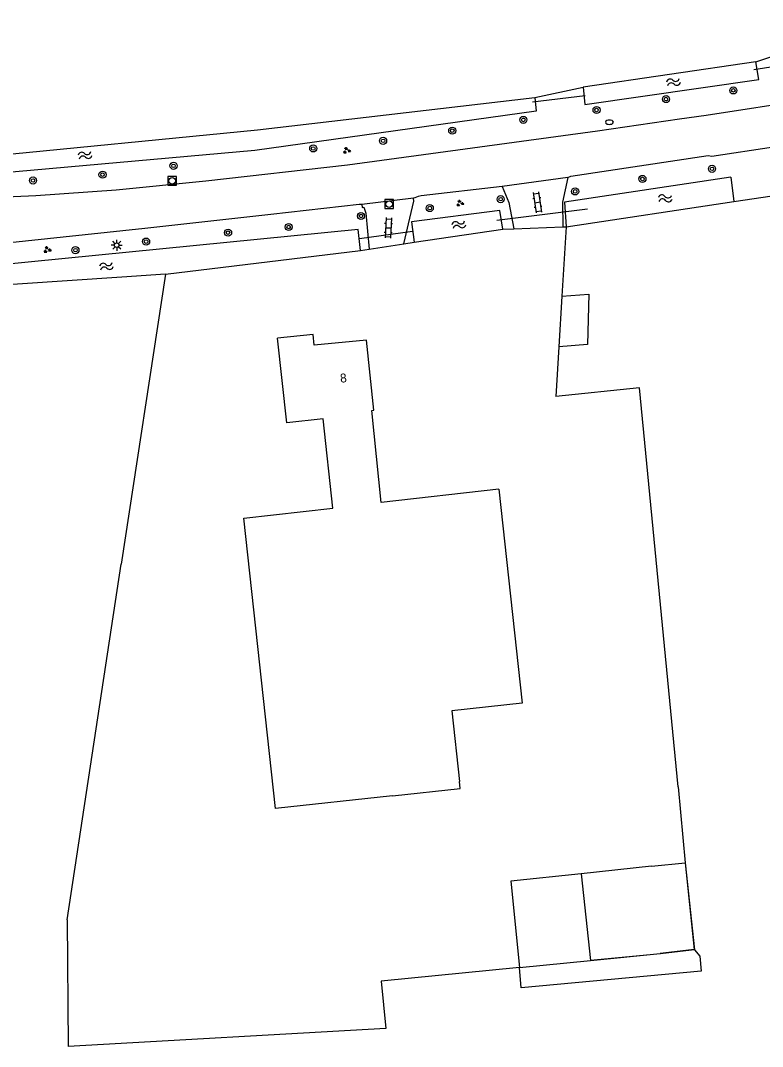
# Model space of a CAD drawing. Extents: x 124000 to 129000, y 395500 to 397503.
# Drawn here: x 125043 to 125126.8, y 396182.9 to 396298.7 of the extents above; entities that cross this region are included whole.
import ezdxf

# ---------------------------------------------------------------- set-up
doc = ezdxf.new("R2010")
doc.units = 0
for name, color, linetype in [('gg-afsc-hekwerk', 7, 'Continuous'), ('gg-anno-huisnummerreeks BGT', 7, 'Continuous'), ('gg-bbg-bijgebouw', 7, 'Continuous'), ('gg-bbg-gedigitaliseerde bebouwing', 7, 'Continuous'), ('gg-bbg-gedigitaliseerde bijgebouw', 7, 'Continuous'), ('gg-bbg-hoofdgebouw', 7, 'Continuous'), ('gg-bbg-luifel en loopbrug', 7, 'Continuous'), ('gg-knt-bronhoudergrens', 7, 'Continuous'), ('gg-knt-verharding', 7, 'Continuous'), ('gg-kntw-bovenkant insteek waterloop', 7, 'Continuous'), ('gg-kwrk-duiker nz buis', 7, 'Continuous'), ('gt-grn-groengrens', 7, 'Continuous'), ('gt-grn-weggrens', 7, 'Continuous'), ('gt-symb-boom', 7, 'Continuous'), ('gt-symb-brandkraan', 7, 'Continuous'), ('gt-symb-groenvak', 7, 'Continuous'), ('gt-symb-klinker verharding', 7, 'Continuous'), ('gt-symb-lichtmast', 7, 'Continuous'), ('gt-symb-rioolschacht', 7, 'Continuous'), ('gt-symb-watersymbool', 7, 'Continuous'), ('gx-grn-maaiveld', 7, 'Continuous')]:
    doc.layers.add(name, color=color, linetype=linetype)

# ---------------------------------------------------------------- blocks, each defined once
blk = doc.blocks.new('gt0-BOOM')
at = {"layer": 'gt-symb-boom'}
for radius in [0.4, 0.2]:
    blk.add_circle((0, 0), radius, dxfattribs=at)
blk = doc.blocks.new('gt0-WA')
at = {"layer": 'gt-symb-watersymbool'}
for centre, start, end in [((-0.32, 0.02), 28.0725, 151.9275), ((0.43, 0.42), 208.0725, 331.9275), ((-0.32, -0.43), 28.0725, 151.9275), ((0.43, -0.03), 208.0725, 331.9275)]:
    blk.add_arc(centre, 0.425, start, end, dxfattribs=at)
blk = doc.blocks.new('gt0-BR')
at = {"layer": 'gt-symb-brandkraan'}
for centre, radius, start, end in [((-0.24, 0), 0.206, 107.5669, 252.4331), ((0.6, -2.66), 3, 106.892, 107.5669), ((0, -0.69), 0.938, 73.108, 106.892), ((-0.6, -2.66), 3, 72.4331, 73.108), ((0.24, 0), 0.206, 287.567, 72.4331), ((0.6, 2.66), 3, 252.4331, 253.108), ((0, 0.69), 0.938, 253.108, 286.8921), ((-0.6, 2.66), 3, 286.8921, 287.567)]:
    blk.add_arc(centre, radius, start, end, dxfattribs=at)
blk = doc.blocks.new('gt0-GRVAK')
at = {"layer": 'gt-symb-groenvak'}
for p, q in [((-0.11, 0.19), (-0.23, 0.24)), ((-0.18, 0.15), (0.09, 0.15)), ((-0.09, 0.21), (-0.16, 0.32)), ((-0.05, 0.21), (-0.05, 0.39)), ((0, 0.21), (0.06, 0.32)), ((0.01, 0.19), (0.13, 0.24)), ((0.26, -0.05), (0.2, 0.06)), ((0.3, -0.05), (0.3, 0.13)), ((0.35, -0.05), (0.41, 0.06)), ((-0.25, -0.23), (-0.36, -0.18)), ((-0.32, -0.26), (-0.05, -0.26)), ((-0.23, -0.21), (-0.29, -0.09)), ((-0.18, -0.2), (-0.18, -0.02)), ((-0.14, -0.21), (-0.07, -0.09)), ((-0.12, -0.23), (0, -0.18)), ((0.24, -0.07), (0.12, -0.02)), ((0.17, -0.11), (0.44, -0.11)), ((0.37, -0.07), (0.49, -0.02))]:
    blk.add_line(p, q, dxfattribs=at)
blk = doc.blocks.new('gt0-KL1')
at = {"layer": 'gt-symb-klinker verharding'}
for p, q in [((-1.15, 0.3), (1.15, 0.3)), ((-1, -0.3), (-1, 0.3)), ((-0.5, 0.3), (-0.5, 0.45)), ((0, -0.3), (0, 0.3)), ((0.5, 0.3), (0.5, 0.45)), ((1, -0.3), (1, 0.3)), ((-1.15, -0.3), (1.15, -0.3)), ((-0.5, -0.45), (-0.5, -0.3)), ((0.5, -0.45), (0.5, -0.3))]:
    blk.add_line(p, q, dxfattribs=at)
blk = doc.blocks.new('gt0-RS')
at = {"layer": 'gt-symb-rioolschacht'}
blk.add_lwpolyline([(-0.5, -0.5), (0.5, -0.5), (0.5, 0.5), (-0.5, 0.5)], close=True, dxfattribs=at)
blk.add_circle((0, 0), 0.375, dxfattribs=at)
blk = doc.blocks.new('gt0-LMAST')
at = {"layer": 'gt-symb-lichtmast'}
for p, q in [((-0.18, 0.17), (-0.45, 0.44)), ((-0.01, 0.25), (-0.01, 0.62)), ((0.17, 0.17), (0.44, 0.44)), ((-0.26, 0), (-0.63, 0)), ((-0.18, -0.18), (-0.45, -0.45)), ((-0.01, -0.25), (-0.01, -0.63)), ((0.44, -0.45), (0.17, -0.18)), ((0.24, 0), (0.62, 0))]:
    blk.add_line(p, q, dxfattribs=at)
blk.add_circle((-0.01, 0), 0.25, dxfattribs=at)

msp = doc.modelspace()

# ---------------------------------------------------------------- linework, layer by layer
at = {"layer": 'gg-afsc-hekwerk'}
for p, q in [((125123.53, 396278.23), (125128.9, 396279.04)), ((125123.53, 396278.23), (125128.9, 396279.04)), ((125104.6, 396275.38), (125123.53, 396278.23)), ((125104.6, 396275.38), (125123.53, 396278.23)), ((125104.6, 396275.38), (125104.12, 396267.53)), ((125104.6, 396275.38), (125104.12, 396267.53)), ((125059.35, 396270.03), (125054.36, 396237.31)), ((125059.35, 396270.03), (125054.36, 396237.31)), ((125059.35, 396270.03), (125054.41, 396269.7)), ((125059.35, 396270.03), (125054.41, 396269.7)), ((125104.12, 396267.53), (125103.77, 396261.82)), ((125103.77, 396261.82), (125103.43, 396256.23)), ((125103.77, 396261.82), (125103.43, 396256.23)), ((125048.24, 396197.18), (125054.36, 396237.31)), ((125048.24, 396197.18), (125054.36, 396237.31)), ((125084.22, 396184.9), (125048.34, 396182.87)), ((125084.22, 396184.9), (125048.34, 396182.87))]:
    msp.add_line(p, q, dxfattribs=at)
for points in [[(125054.41, 396269.7), (125025.77, 396267.78), (125023.5, 396267.74)], [(125054.41, 396269.7), (125025.77, 396267.78), (125023.5, 396267.74)], [(125099.32, 396191.79), (125083.7, 396190.24), (125084.22, 396184.9)], [(125099.32, 396191.79), (125083.7, 396190.24), (125084.22, 396184.9)]]:
    msp.add_lwpolyline(points, dxfattribs=at)
at = {"layer": 'gg-bbg-bijgebouw'}
msp.add_line((125099.32, 396191.79), (125107.37, 396192.58), dxfattribs=at)
msp.add_lwpolyline([(125106.31, 396202.37), (125098.35, 396201.53), (125099.32, 396191.79)], dxfattribs=at)
at = {"layer": 'gg-bbg-gedigitaliseerde bebouwing'}
for points in [[(125084.98, 396211.15), (125071.79, 396209.71), (125068.2, 396242.51), (125078.25, 396243.61), (125077.15, 396253.69), (125073.04, 396253.24), (125072, 396262.79)], [(125097.01, 396245.75), (125099.65, 396221.63), (125091.68, 396220.76), (125092.56, 396212.77)], [(125084.98, 396211.15), (125092.64, 396211.99), (125092.56, 396212.77)]]:
    msp.add_lwpolyline(points, dxfattribs=at)
at = {"layer": 'gg-bbg-gedigitaliseerde bijgebouw'}
msp.add_line((125106.31, 396202.37), (125107.37, 396192.58), dxfattribs=at)
at = {"layer": 'gg-bbg-hoofdgebouw'}
msp.add_lwpolyline([(125097.01, 396245.75), (125083.7, 396244.26), (125082.64, 396254.66), (125082.87, 396254.68), (125082.06, 396262.58), (125076.15, 396262.02), (125076.02, 396263.22), (125072, 396262.79)], dxfattribs=at)
at = {"layer": 'gg-bbg-luifel en loopbrug'}
for p, q in [((125114.26, 396203.21), (125106.31, 396202.37)), ((125107.37, 396192.58), (125115.24, 396193.36))]:
    msp.add_line(p, q, dxfattribs=at)
msp.add_lwpolyline([(125114.26, 396203.21), (125118.03, 396203.58), (125119.06, 396193.8), (125115.24, 396193.36)], dxfattribs=at)
at = {"layer": 'gg-knt-bronhoudergrens'}
for p, q in [((125112.89, 396257.22), (125103.43, 396256.23)), ((125117.27, 396212.16), (125112.89, 396257.22)), ((125117.27, 396212.16), (125118.03, 396203.58)), ((125118.03, 396203.58), (125119.09, 396193.78)), ((125048.24, 396197.18), (125048.34, 396182.87))]:
    msp.add_line(p, q, dxfattribs=at)
for points in [[(125104.12, 396267.53), (125107.17, 396267.79), (125107, 396262.08), (125103.77, 396261.82)], [(125119.09, 396193.78), (125115.28, 396193.34), (125107.37, 396192.58), (125107.37, 396192.58)]]:
    msp.add_lwpolyline(points, dxfattribs=at)
at = {"layer": 'gg-knt-verharding'}
for p, q in [((125104.8, 396280.95), (125097.37, 396279.91)), ((125104.8, 396280.95), (125104.2, 396278.17)), ((125097.37, 396279.91), (125098.12, 396278.11)), ((125087.36, 396278.62), (125081.51, 396277.88)), ((125098.12, 396278.11), (125098.7, 396275.16)), ((125104.2, 396278.17), (125104.23, 396275.36)), ((125081.97, 396276.91), (125082.37, 396272.86)), ((125086.28, 396273.46), (125086.95, 396276.34))]:
    msp.add_line(p, q, dxfattribs=at)
for points in [[(125104.8, 396280.95), (125105.15, 396281.11), (125120.65, 396283.43), (125121.06, 396283.34), (125128.01, 396284.42), (125128.61, 396284.61), (125136.66, 396285.82), (125142.62, 396286.78), (125160.68, 396289.82), (125176.32, 396292.49), (125194.56, 396295.7), (125211.24, 396298.66), (125211.93, 396298.5), (125212.07, 396298.52)], [(125140.56, 396291.15), (125132.12, 396289.75), (125120.41, 396287.95), (125117.39, 396287.53), (125108.14, 396286.18), (125079.9, 396282.33), (125063.91, 396280.52), (125053.77, 396279.53), (125044.71, 396278.88), (125032.89, 396278.35), (125030.16, 396278.36), (125027.64, 396278.48)], [(125097.37, 396279.91), (125088.23, 396278.87), (125087.88, 396278.78), (125087.51, 396278.64), (125087.36, 396278.62)], [(125086.95, 396276.34), (125087.4, 396278.27), (125087.36, 396278.62)], [(125081.51, 396277.88), (125081.23, 396277.91), (125071.24, 396276.75), (125057, 396275.2), (125036.75, 396273.05), (125033.1, 396272.75)], [(125081.51, 396277.88), (125081.56, 396277.57), (125081.76, 396277.59), (125081.97, 396276.91)]]:
    msp.add_lwpolyline(points, dxfattribs=at)
at = {"layer": 'gg-kntw-bovenkant insteek waterloop'}
for p, q in [((125126.02, 396294), (125106.51, 396291.14)), ((125123.22, 396280.99), (125123.53, 396278.23)), ((125087.42, 396273.64), (125097.45, 396275.12)), ((125059.35, 396270.03), (125081.37, 396272.7))]:
    msp.add_line(p, q, dxfattribs=at)
for points in [[(125106.51, 396291.14), (125106.7, 396289.17), (125126.36, 396292.01), (125126.02, 396294)], [(125031.31, 396283.03), (125038.21, 396283.22), (125069.74, 396286.33), (125101.05, 396289.98)], [(125101.05, 396289.98), (125101.21, 396288.41), (125069.43, 396283.98), (125038.57, 396281.24), (125033.84, 396281.14)], [(125123.22, 396280.99), (125104.42, 396278.16), (125104.6, 396275.38)], [(125097.45, 396275.12), (125097.13, 396277.22), (125087.15, 396275.93), (125087.42, 396273.64)], [(125081.37, 396272.7), (125081.12, 396275.09), (125040.39, 396271.06), (125023.35, 396270.19), (125023.5, 396267.74)]]:
    msp.add_lwpolyline(points, dxfattribs=at)
at = {"layer": 'gg-kwrk-duiker nz buis'}
for p, q in [((125125.79, 396293.13), (125130.25, 396293.82)), ((125106.75, 396290.17), (125100.82, 396289.45)), ((125107.03, 396277.37), (125096.78, 396276.08)), ((125081.25, 396274.04), (125087.24, 396274.87))]:
    msp.add_line(p, q, dxfattribs=at)
at = {"layer": 'gt-grn-groengrens'}
for p, q in [((125126.02, 396294), (125129.36, 396295.08)), ((125101.05, 396289.98), (125106.51, 396291.14)), ((125097.45, 396275.12), (125098.7, 396275.16)), ((125104.23, 396275.36), (125104.6, 396275.38)), ((125081.37, 396272.7), (125082.37, 396272.86)), ((125086.28, 396273.46), (125087.42, 396273.64))]:
    msp.add_line(p, q, dxfattribs=at)
at = {"layer": 'gt-grn-weggrens'}
for p, q in [((125098.7, 396275.16), (125104.23, 396275.36)), ((125082.37, 396272.86), (125086.28, 396273.46))]:
    msp.add_line(p, q, dxfattribs=at)
at = {"layer": 'gx-grn-maaiveld'}
msp.add_lwpolyline([(125119.09, 396193.78), (125119.7, 396193.05), (125119.86, 396191.36), (125099.51, 396189.48), (125099.32, 396191.79)], dxfattribs=at)

# ---------------------------------------------------------------- block references
at = {"layer": 'gt-symb-boom'}
for p in [(125115.89, 396289.79), (125123.49, 396290.77), (125108.04, 396288.56), (125099.77, 396287.44), (125091.74, 396286.23), (125076.04, 396284.22), (125083.93, 396285.08), (125060.26, 396282.26), (125121.08, 396281.92), (125044.39, 396280.6), (125052.24, 396281.26), (125113.22, 396280.78), (125105.62, 396279.37), (125097.21, 396278.5), (125089.2, 396277.49), (125081.43, 396276.6), (125066.42, 396274.72), (125073.27, 396275.35), (125057.16, 396273.71), (125049.18, 396272.74)]:
    msp.add_blockref('gt0-BOOM', p, dxfattribs=at)
at = {"layer": 'gt-symb-brandkraan'}
msp.add_blockref('gt0-BR', (125109.49, 396287.18), dxfattribs=at)
at = {"layer": 'gt-symb-groenvak'}
for p in [(125079.81, 396283.99), (125092.6, 396278.03), (125045.98, 396272.79)]:
    msp.add_blockref('gt0-GRVAK', p, dxfattribs=at)
at = {"layer": 'gt-symb-klinker verharding'}
for p, rotation in [((125101.36, 396278.14), -81.72410717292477), ((125084.53, 396275.26), -92.92247266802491)]:
    msp.add_blockref('gt0-KL1', p, dxfattribs=dict(at, rotation=rotation))
at = {"layer": 'gt-symb-lichtmast'}
msp.add_blockref('gt0-LMAST', (125053.85, 396273.3), dxfattribs=at)
at = {"layer": 'gt-symb-rioolschacht'}
for p in [(125060.1, 396280.57), (125084.61, 396277.94)]:
    msp.add_blockref('gt0-RS', p, dxfattribs=at)
at = {"layer": 'gt-symb-watersymbool'}
for p, rotation in [((125116.67, 396291.69), 16.20518536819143), ((125050.21, 396283.43), 16.205185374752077), ((125115.74, 396278.58), 8.51093419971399), ((125092.43, 396275.6), 16.205185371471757), ((125052.62, 396270.9), 16.205185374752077)]:
    msp.add_blockref('gt0-WA', p, dxfattribs=dict(at, rotation=rotation))

# ---------------------------------------------------------------- texts
at = {"layer": 'gg-anno-huisnummerreeks BGT'}
msp.add_text('8', height=1, rotation=5.4, dxfattribs=at).set_placement((125079.12, 396257.78))

doc.saveas('drawing.dxf')
